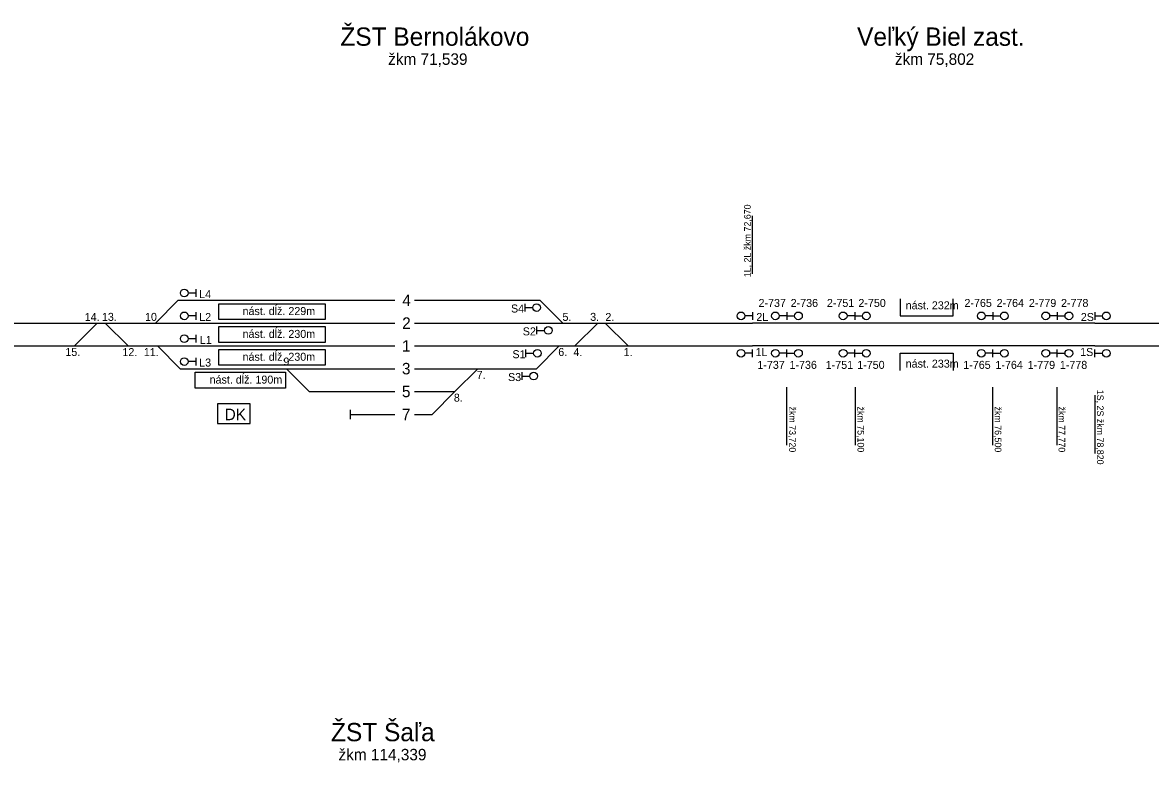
# Model space of a CAD drawing. Extents: x -119 to 851, y -238 to 59.
# Drawn here: x 52.5 to 151.1, y -84.9 to -20.1 of the extents above; entities that cross this region are included whole.
import ezdxf

# ---------------------------------------------------------------- set-up
doc = ezdxf.new("R2010")
doc.units = 0
for name, color, linetype in [('budova', 7, 'Continuous'), ('Level 2', 7, 'Continuous'), ('nastupistia', 7, 'Continuous'), ('netlač', 7, 'Continuous'), ('popisky navestidla', 7, 'Continuous'), ('popisky stanic a zastavok', 7, 'Continuous'), ('PU_navestidla', 7, 'Continuous'), ('PU_oznacenie navestidiel', 7, 'Continuous'), ('PU_stan_kolaje', 7, 'Continuous')]:
    doc.layers.add(name, color=color, linetype=linetype)

msp = doc.modelspace()

# ---------------------------------------------------------------- linework, layer by layer
at = {"layer": 'budova'}
msp.add_lwpolyline([(69.501, -55.245), (72.368, -55.245), (72.368, -53.496), (69.501, -53.496)], close=True, dxfattribs=at)
at = {"layer": 'Level 2'}
for p, q in [((66.069, -44.449), (85.004, -44.449)), ((86.728, -44.449), (97.694, -44.449)), ((47.916, -46.448), (53.832, -46.448)), ((53.832, -46.448), (70.03, -46.448)), ((70.03, -46.448), (85.004, -46.448)), ((86.728, -46.448), (93.627, -46.448)), ((93.627, -46.448), (116.296, -46.448)), ((146.229, -46.448), (164.942, -46.448)), ((47.916, -48.447), (68.83, -48.447)), ((68.83, -48.447), (85.004, -48.447)), ((86.728, -48.447), (94.627, -48.447)), ((94.627, -48.447), (112.924, -48.447)), ((112.924, -48.447), (116.296, -48.447)), ((146.229, -48.447), (179.94, -48.447)), ((66.249, -50.446), (85.004, -50.446)), ((86.728, -50.446), (97.393, -50.446)), ((77.522, -52.445), (85.004, -52.445)), ((86.728, -52.445), (90.264, -52.445)), ((81.145, -54.844), (81.145, -54.044)), ((81.145, -54.444), (85.004, -54.444)), ((86.728, -54.444), (88.265, -54.444))]:
    msp.add_line(p, q, dxfattribs=at)
at = {"layer": 'nastupistia'}
for points in [[(129.207, -44.308), (129.207, -45.812), (133.846, -45.812), (133.846, -44.308)], [(129.209, -50.586), (129.209, -49.082), (133.846, -49.082), (133.846, -50.586)]]:
    msp.add_lwpolyline(points, dxfattribs=at)
for points in [[(78.933, -46.136), (69.61, -46.136), (69.61, -44.751), (78.933, -44.751)], [(78.933, -48.135), (69.61, -48.135), (69.61, -46.75), (78.933, -46.75)], [(78.933, -50.134), (69.61, -50.134), (69.61, -48.749), (78.933, -48.749)], [(75.46, -52.133), (67.552, -52.133), (67.552, -50.748), (75.46, -50.748)]]:
    msp.add_lwpolyline(points, close=True, dxfattribs=at)
at = {"layer": 'netlač'}
for p, q in [((146.229, -46.448), (116.296, -46.448)), ((146.229, -48.447), (116.296, -48.447))]:
    msp.add_line(p, q, dxfattribs=at)
at = {"layer": 'popisky navestidla'}
for p, q in [((116.296, -42.136), (116.296, -37.045)), ((119.272, -52.046), (119.272, -57.137)), ((125.259, -52.046), (125.259, -57.137)), ((137.283, -52.046), (137.283, -57.137)), ((142.918, -52.046), (142.918, -57.137)), ((146.229, -52.761), (146.229, -57.852))]:
    msp.add_line(p, q, dxfattribs=at)
at = {"layer": 'PU_navestidla'}
for p, q in [((67.605, -43.815), (66.933, -43.815)), ((67.605, -43.477), (67.605, -44.149)), ((96.403, -45.421), (96.403, -44.749)), ((96.403, -45.084), (97.075, -45.084)), ((67.605, -45.814), (66.933, -45.814)), ((67.605, -45.476), (67.605, -46.148)), ((116.296, -45.814), (115.624, -45.814)), ((116.296, -45.476), (116.296, -46.148)), ((119.306, -45.813), (118.634, -45.813)), ((119.306, -45.475), (119.306, -46.147)), ((119.306, -45.475), (119.306, -46.147)), ((119.306, -45.813), (119.978, -45.813)), ((125.23, -45.813), (124.558, -45.813)), ((125.23, -45.475), (125.23, -46.147)), ((125.23, -45.475), (125.23, -46.147)), ((125.23, -45.813), (125.902, -45.813)), ((137.317, -45.813), (136.645, -45.813)), ((137.317, -45.475), (137.317, -46.147)), ((137.317, -45.475), (137.317, -46.147)), ((137.317, -45.813), (137.989, -45.813)), ((142.952, -45.813), (142.28, -45.813)), ((142.952, -45.475), (142.952, -46.147)), ((142.952, -45.475), (142.952, -46.147)), ((142.952, -45.813), (143.624, -45.813)), ((146.229, -45.476), (146.229, -46.148)), ((146.229, -45.814), (146.901, -45.814)), ((97.433, -47.42), (97.433, -46.748)), ((97.433, -47.083), (98.105, -47.083)), ((67.605, -47.813), (66.933, -47.813)), ((67.605, -47.475), (67.605, -48.147)), ((96.475, -49.419), (96.475, -48.747)), ((96.475, -49.082), (97.147, -49.082)), ((116.296, -49.082), (115.624, -49.082)), ((116.296, -49.419), (116.296, -48.747)), ((119.306, -49.081), (118.634, -49.081)), ((119.306, -49.418), (119.306, -48.746)), ((119.306, -49.418), (119.306, -48.746)), ((119.306, -49.081), (119.978, -49.081)), ((125.23, -49.081), (124.558, -49.081)), ((125.23, -49.418), (125.23, -48.746)), ((125.23, -49.418), (125.23, -48.746)), ((125.23, -49.081), (125.902, -49.081)), ((137.317, -49.081), (136.645, -49.081)), ((137.317, -49.418), (137.317, -48.746)), ((137.317, -49.418), (137.317, -48.746)), ((137.317, -49.081), (137.989, -49.081)), ((142.952, -49.081), (142.28, -49.081)), ((142.952, -49.418), (142.952, -48.746)), ((142.952, -49.418), (142.952, -48.746)), ((142.952, -49.081), (143.624, -49.081)), ((146.229, -49.421), (146.229, -48.749)), ((146.229, -49.083), (146.901, -49.083)), ((67.605, -49.812), (66.933, -49.812)), ((67.605, -49.474), (67.605, -50.146)), ((96.147, -51.418), (96.147, -50.746)), ((96.147, -51.081), (96.819, -51.081))]:
    msp.add_line(p, q, dxfattribs=at)
for centre in [(66.597, -43.813), (97.411, -45.085), (66.597, -45.812), (115.288, -45.812), (118.298, -45.811), (120.314, -45.811), (124.222, -45.811), (126.238, -45.811), (136.309, -45.811), (138.325, -45.811), (141.944, -45.811), (143.96, -45.811), (147.237, -45.812), (98.441, -47.084), (66.597, -47.811), (97.483, -49.083), (115.288, -49.083), (118.298, -49.082), (120.314, -49.082), (124.222, -49.082), (126.238, -49.082), (136.309, -49.082), (138.325, -49.082), (141.944, -49.082), (143.96, -49.082), (147.237, -49.085), (66.597, -49.81), (97.155, -51.082)]:
    msp.add_circle(centre, 0.336, dxfattribs=at)
at = {"layer": 'PU_stan_kolaje'}
for points in [[(66.069, -44.449), (64.07, -46.448)], [(97.694, -44.449), (99.693, -46.448)], [(58.989, -46.448), (56.99, -48.447)], [(59.685, -46.448), (61.684, -48.447)], [(102.763, -46.448), (100.764, -48.447)], [(103.415, -46.448), (105.414, -48.447)], [(64.25, -48.447), (66.247, -50.444)], [(99.392, -48.447), (97.393, -50.446)], [(75.523, -50.446), (77.52, -52.443)], [(92.263, -50.446), (90.264, -52.445)], [(90.264, -52.445), (88.265, -54.444)]]:
    msp.add_lwpolyline(points, dxfattribs=at)

# ---------------------------------------------------------------- texts
at = {"layer": 'budova'}
msp.add_text('DK', height=1.0044, dxfattribs=at).set_placement((70.13, -54.94))
at = {"layer": 'nastupistia'}
for s, p in [('nást. dĺž. 229m', (71.695, -45.742)), ('nást. 232m', (129.691, -45.24)), ('nást. dĺž. 230m', (71.695, -47.741)), ('nást. dĺž. 230m', (71.695, -49.74)), ('nást. 233m', (129.691, -50.342)), ('nást. dĺž. 190m', (68.814, -51.739))]:
    msp.add_text(s, height=0.7, dxfattribs=at).set_placement(p)
at = {"layer": 'popisky navestidla'}
for s, height, rotation, p in [('1L, 2L žkm 72,670', 0.57931, 90, (116.139, -42.435)), ('1S, 2S žkm 78,820', 0.57931, 270, (146.421, -52.28)), ('žkm 73,720', 0.5793, 270, (119.5, -53.745)), ('žkm 75,100', 0.5793, 270, (125.475, -53.745)), ('žkm 76,500', 0.5793, 270, (137.481, -53.745)), ('žkm 77,770', 0.5793, 270, (143.059, -53.745))]:
    msp.add_text(s, height=height, rotation=rotation, dxfattribs=at).set_placement(p)
at = {"layer": 'popisky stanic a zastavok'}
for s, height, p in [('ŽST Bernolákovo', 1.6, (80.249, -22.179)), ('Veľký Biel zast.', 1.6, (125.44, -22.179)), ('žkm 71,539', 1.0044, (84.425, -23.847)), ('žkm 75,802', 1.0044, (128.745, -23.847)), ('ŽST Šaľa', 1.6, (79.432, -83.035)), ('žkm 114,339', 1.00438, (80.086, -84.704))]:
    msp.add_text(s, height=height, dxfattribs=at).set_placement(p)
at = {"layer": 'PU_oznacenie navestidiel'}
for s, p in [('L4', (67.904, -44.263)), ('2-737', (116.821, -45.033)), ('2-736', (119.631, -45.033)), ('2-751', (122.8, -45.033)), ('2-750', (125.555, -45.033)), ('2-765', (134.83, -45.033)), ('2-764', (137.643, -45.033)), ('2-779', (140.466, -45.033)), ('2-778', (143.276, -45.033)), ('S4', (95.171, -45.52)), ('14.', (57.887, -46.262)), ('13.', (59.395, -46.25)), ('10.', (63.164, -46.25)), ('L2', (67.906, -46.262)), ('5.', (99.673, -46.25)), ('3.', (102.099, -46.25)), ('2.', (103.424, -46.262)), ('2L', (116.625, -46.262)), ('2S', (145.011, -46.262)), ('S2', (96.202, -47.519)), ('L1', (67.959, -48.261)), ('15.', (56.196, -49.321)), ('12.', (61.185, -49.333)), ('11.', (63.058, -49.333)), ('S1', (95.298, -49.518)), ('6.', (99.306, -49.321)), ('4.', (100.632, -49.333)), ('1.', (105.018, -49.333)), ('1L', (116.562, -49.333)), ('1S', (144.948, -49.323)), ('L3', (67.904, -50.248)), ('9', (75.268, -50.158)), ('1-737', (116.72, -50.45)), ('1-736', (119.529, -50.45)), ('1-751', (122.698, -50.45)), ('1-750', (125.453, -50.45)), ('1-765', (134.728, -50.45)), ('1-764', (137.541, -50.45)), ('1-779', (140.364, -50.45)), ('1-778', (143.174, -50.45)), ('7.', (92.169, -51.332)), ('S3', (94.914, -51.517)), ('8.', (90.175, -53.319))]:
    msp.add_text(s, height=0.7, dxfattribs=at).set_placement(p)
at = {"layer": 'PU_stan_kolaje'}
for s, p in [('4', (85.668, -44.951)), ('2', (85.652, -46.95)), ('1', (85.637, -48.949)), ('3', (85.634, -50.931)), ('5', (85.631, -52.93)), ('7', (85.627, -54.946))]:
    msp.add_text(s, height=1.004, dxfattribs=at).set_placement(p)

doc.saveas('drawing.dxf')
